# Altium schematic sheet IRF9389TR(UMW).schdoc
size 127 x 101 mm
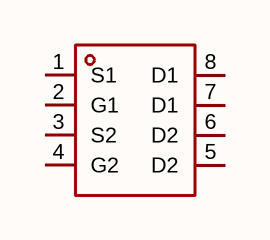
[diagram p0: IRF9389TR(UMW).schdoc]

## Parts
Q?  irf9389tr(umw)  [SOIC-8_L4.9-W3.9-P1.27-LS6.0-BL]  (value not drawn)

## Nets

Not connected (* = marked no-connect by the designer): Q? 1(S1) 2(G1) 3(S2) 4(G2) 5(D2) 6(D2) 7(D1) 8(D1)

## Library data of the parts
Q? = irf9389tr(umw): 漏源电压(Vdss):30V;连续漏极电流(Id):6.8A;导通电阻(RDS(on)):-;耗散功率(Pd):2W;阈值电压(Vgs(th)):1.3V;; Manufacturer: UMW(友台半导体); AddInBom: yes; ModelId: e81d2f7d937b4a6ab1dca543ff5d56a4; ModelName: SOIC-8_L4.9-W3.9-H1.7-LS6.0-P1.27; ModelTransform: 192.913,236.22,0,0,0,0,0,0,0; Drain to Source Voltage: 30V; Current - Continuous Drain(Id): 6.8A; Pd - Power Dissipation: 2W; Gate Threshold Voltage (Vgs(th)): 1.3V; Gate Charge(Qg): 14nC@10V; Input Capacitance(Ciss): 398pF; Reverse Transfer Capacitance (Crss@Vds): 36pF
